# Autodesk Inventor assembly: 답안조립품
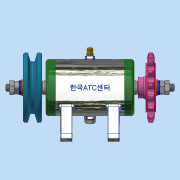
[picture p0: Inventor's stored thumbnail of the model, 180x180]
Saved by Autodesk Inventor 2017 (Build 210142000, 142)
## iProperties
Part Number: 답안조립품
Material: 일반
Document SubType Name: Assembly
Designer: Administrator
Author: Administrator
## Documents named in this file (16)
- C:\Users\Administrator\Desktop\711206V1013\답안조립품.iam
- C:\Users\Administrator\Desktop\711206V1013\V벨트풀리.ipt
- C:\Users\Administrator\Desktop\711206V1013\너트 M8.ipt
- C:\Users\Administrator\Desktop\711206V1013\니플 M6 x 0.75.ipt
- C:\Users\Administrator\Desktop\711206V1013\베어링 6002.ipt
- C:\Users\Administrator\Desktop\711206V1013\본체.ipt
- C:\Users\Administrator\Desktop\711206V1013\볼트 M4 x 12.ipt
- C:\Users\Administrator\Desktop\711206V1013\볼트 M6 x 8.ipt
- C:\Users\Administrator\Desktop\711206V1013\스프로킷.ipt
- C:\Users\Administrator\Desktop\711206V1013\스프링와셔 8.ipt
- C:\Users\Administrator\Desktop\711206V1013\오일 실 15 x 25 x 7.ipt
- C:\Users\Administrator\Desktop\711206V1013\와셔 6 x 11.5.ipt
- C:\Users\Administrator\Desktop\711206V1013\와셔 8 x 17.ipt
- C:\Users\Administrator\Desktop\711206V1013\축.ipt
- C:\Users\Administrator\Desktop\711206V1013\커버.ipt
- C:\Users\Administrator\Desktop\711206V1013\키 3 x 3.ipt
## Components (11 placed, 3 different names)
1. V벨트풀리:1
2. KS B 2023 6002 - 15 x 32 x 9:1
3. KS B 2023 6002 - 15 x 32 x 9:2
4. ISO 4762 M4 x 12:2
5. ISO 4762 M4 x 12:3
6. ISO 4762 M4 x 12:4
7. ISO 4762 M4 x 12:5
8. ISO 4762 M4 x 12:1
9. ISO 4762 M4 x 12:6
10. ISO 4762 M4 x 12:7
11. ISO 4762 M4 x 12:8
